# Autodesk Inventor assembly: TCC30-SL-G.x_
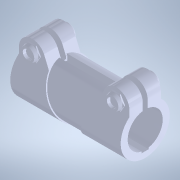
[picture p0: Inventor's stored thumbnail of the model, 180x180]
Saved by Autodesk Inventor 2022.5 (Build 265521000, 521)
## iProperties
Created: 2023-09
Part Number: TCC30-SL-G.x_
Document SubType Name: Assembly
Designer: ImaoCorp
Sending System: SOLIDWORKS 2021-2021301
MC: AMD64
MC_MODEL: Intel64 Family 6 Model 60 Stepping 3, GenuineIntel
OS: Windows_NT
FRU: Parasolid Version 32.1, build 255,  1- 1-2021
FORMAT: text
GUISE: transmit
KEY: TCC30-SL-G
FILE: TCC30-SL-G.x_t
DATE: Fri Sep 15 15:37:12 2023
Author: ImaoCorp
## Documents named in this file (6)
- X:\14_SW2022-Inv2022\00_全2023-1023新製品(TCC)まで\t\tcc30-sl-g\TCC30-SL-G.iam
- X:\14_SW2022-Inv2022\00_全2023-1023新製品(TCC)まで\t\tcc30-sl-g\TCC30-SL-G_01.ipt
- X:\14_SW2022-Inv2022\00_全2023-1023新製品(TCC)まで\t\tcc30-sl-g\TCC30-SL-G_02.ipt
- X:\14_SW2022-Inv2022\00_全2023-1023新製品(TCC)まで\t\tcc30-sl-g\TCC30-SL-G_03.ipt
- X:\14_SW2022-Inv2022\00_全2023-1023新製品(TCC)まで\t\tcc30-sl-g\TCC30-SL-G_04.ipt
- X:\14_SW2022-Inv2022\00_全2023-1023新製品(TCC)まで\t\tcc30-sl-g\TCC30-SL-G_05.ipt
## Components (5 placed, 5 different names)
1. TCC30-SL-G_01
2. TCC30-SL-G_02
3. TCC30-SL-G_03
4. TCC30-SL-G_04
5. TCC30-SL-G_05
